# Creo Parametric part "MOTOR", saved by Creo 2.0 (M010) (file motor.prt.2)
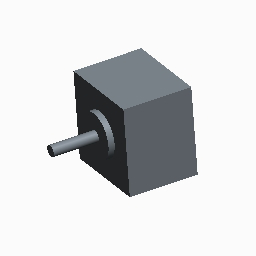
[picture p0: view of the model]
Units: Inch lbm Second (Pro/E Default); INCH, POUND, SECS

Created from: INLBS_PART_SOLID.PRT

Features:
  1. datum plane "RIGHT"
  2. datum plane "TOP"
  3. datum plane "FRONT"
  4. coordinate system
  5. sketch "Sketch 1"
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
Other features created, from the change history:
  extrusion "Extrude 1"
  sketch "Sketch 2"
  extrusion "Extrude 2"
  sketch "Sketch 3"
  extrusion "Extrude 3"

Surfaces: 11 plane, 4 cylinder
